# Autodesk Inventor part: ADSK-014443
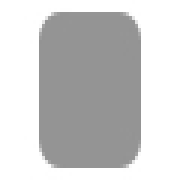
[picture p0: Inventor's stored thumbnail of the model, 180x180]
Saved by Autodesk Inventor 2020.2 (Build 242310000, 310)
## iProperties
Created: 2019-01
Part Number: ADSK-014443
Material: Stahl, weich
Document SubType Name: Modeling
Designer: lutzd
Language: de-DE
Size Designation: 5 x 40 x 40
Categories: <MemberInstance><Categories><Category DisplayName="Sonstige Bauteile" InternalName="5aa15e00-363f-49f2-933f-16f664388e3f" Mnemonic="OTHER"><Category DisplayName
Mass: 61.9577 g
Surface Area: 39.1416 cm^2
Volume: 7.8927 cm^3
Density: 7.85 g/cm^3
Appearance: Semi-Polished(8)
DocNumber: ADSK-014443
Folder: 01 - Themengebiete\Simplification\01 - Packaging machine\
VDS_Category: 3D Komponenten
VDS_NumSchm: Autodesk
Mass: 0,062 kg
VLT_Material: Stahl, weich
IsCustomPart: 1
Title: end cap
Author: lutzd
Revision Number: -
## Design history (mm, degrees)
sketch "Sketch1"
  geometry: L1 (0, 20.175)-(0, -21.446); L2 (-20.203, 0)-(20.169, 0); L3 (-20, 20)-(20, 20); L4 (20, 20)-(20, -20); L5 (20, -20)-(-20, -20); L6 (-20, -20)-(-20, 20); 1 further point
  constraints: 12 end point, 2 horizontal, 2 parallel, 2 point on line, 1 perpendicular, 1 vertical
  dimensions: "d0" = 40 distance between parallel lines of L5 L3 (= height); "d1" = 20 distance between parallel lines of L2 L3 (= 0.5 x height); "d2" = 40 distance between parallel lines of L6 L4 (= width); "d3" = 20 distance between parallel lines of L6 L1 (= 0.5 x width)
extrude "Extrusion1" new body sketch "Sketch1" distance "d4" = 5 (= thickness); taper "d5" = 0 deg
fillet "Fillet1" dims "d6" = 5 (= fillet), "d7" = 0, "fillet" = 5 [user parameter; used in 1 equation term]
chamfer "Chamfer1" distance "d8" = 0 (computed from chamfer); stored, may be unused: second distance "d9" = 2, angle "d10" = 45 deg; dims "d11" = 0, "chamfer" = 0 [user parameter; used in 1 equation term]
body "Solid1"
other parameters: "thickness" = 5 [user parameter; used in 1 equation term], "width" = 40 [user parameter; used in 2 equation terms], "height" = 40 [user parameter; used in 2 equation terms]
